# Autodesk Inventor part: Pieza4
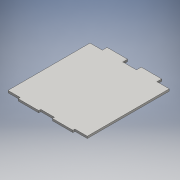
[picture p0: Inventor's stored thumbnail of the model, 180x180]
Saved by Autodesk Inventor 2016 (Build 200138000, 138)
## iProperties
Created: 2016-06
Part Number: Pieza4
Material: Genérico
Document SubType Name: Modeling
Designer: adm
Density: 1 g/cm^3
Appearance: Valor por defecto
Author: adm
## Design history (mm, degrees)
sketch "Boceto1"
  geometry: L1 (-58, -60)-(-58, 60); L2 (58, 60)-(58, -60); L3 (58, -60)-(-58, 60); L4 (-58, -60)-(58, 60); L5 (-10, 60)-(-10, 67); L6 (-10, 67)-(-40, 67); L7 (-40, 67)-(-40, 60); L8 (10, 60)-(10, 67); L9 (10, 67)-(40, 67); L10 (40, 67)-(40, 60); L11 (-10, -60)-(-10, -63); L12 (-10, -63)-(-40, -63); L13 (-40, -63)-(-40, -60); L14 (40, -63)-(40, -60); L15 (10, -63)-(40, -63); L16 (10, -60)-(10, -63); L17 (58, -60)-(40, -60); L18 (40, 60)-(58, 60); L19 (-58, 60)-(-40, 60); L20 (-10, 60)-(10, 60); L21 (10, -60)-(-10, -60); L22 (-40, -60)-(-58, -60); 1 further point
  constraints: 44 end point, 12 parallel, 3 horizontal, 3 perpendicular, 2 midpoint
  dimensions: "d0" = 120 distance of L2.start L2.end; "d1" = 116 distance of L2.end L1.start; "d2" = 18 distance between parallel lines of L1 L7; "d3" = 30 distance of L5.end L6.end; "d6" = 18 distance between parallel lines of L1 L13; "d7" = 30 distance of L11.end L12.end
extrude "Extrusión1" new body sketch "Boceto1" distance "d8" = 3; taper "d9" = 0 deg
node "Sólido1"
other parameters: "d4" = 7
